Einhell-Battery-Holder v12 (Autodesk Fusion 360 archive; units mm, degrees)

design "Einhell-Battery-Holder" references "Base"
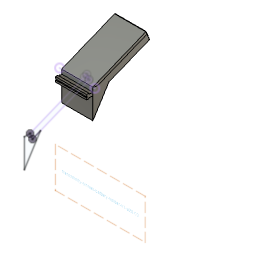
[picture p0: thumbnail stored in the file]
parameter "angle" = 20
component_insert "Component Insert"
sketch "Sketch1" plane through (0, 55.6118, 0) normal (0, 1, 0) x axis (-1, 0, 0)
  line L1 (0, 52.6059) -> (-62, 52.6059)
  line L2 (0, 60) -> (0, 52.6059)
  line L3 (-62, 60) -> (0, 60)
  line L4 (-62, 52.6059) -> (-62, 60)
  line L5 (-62, 60) -> (0, 60)
base_mesh_feature "Base Mesh Feature"
modify "Modify1"
modify "Modify2"
convert_mesh "Convert Mesh" bodies "Einhell_French_Cleat"
delete_face "DeleteFace1"
delete_face "DeleteFace2"
delete_face "DeleteFace3"
delete_face "DeleteFace4"
delete_face "DeleteFace5"
delete_face "DeleteFace6"
delete_face "DeleteFace7"
delete_face "DeleteFace8"
delete_face "DeleteFace9"
delete_face "DeleteFace10"
delete_face "DeleteFace11"
delete_face "DeleteFace12"
delete_face "DeleteFace13"
delete_face "DeleteFace14"
delete_face "DeleteFace15"
delete_face "DeleteFace16"
sketch "Sketch2" plane through (43.2707, 0, 0) normal (1, 0, 0) x axis (0, 1, 0)
  line L1 (75.5556, 48.0301) -> (76.5556, 47.0301)
  line L2 (48.0556, 48.0301) -> (75.5556, 48.0301)
  line L3 (48.0556, 26.0301) -> (48.0556, 48.0301)
  line L4 (65.0556, 43.0301) -> (48.0556, 26.0301)
  line L5 (65.0556, 0.0301) -> (65.0556, 43.0301)
  line L6 (76.5556, 0.0301) -> (65.0556, 0.0301)
  line L7 (76.5556, 47.0301) -> (76.5556, 0.0301)
  line L8 (65.0556, 48.0301) -> (65.0556, 43.0301)
  point P6 (65.0556, 43.0301)
  point P9 (65.0556, 43.0301)
  point P10 (65.0556, 48.0301)
  coincident P6 P9
  coincident L2 P10
  perpendicular L2 L8
extrude "Extrude1" cut sketch "Sketch2" profile of L2 L3 L4 L8 to an object
work_plane "WorkPlane1" AlongDistance -55
split "Split1"
move "Move1"
sketch "Filename" plane through (0, 0, 0) normal (0, 1, 0) x axis (1, 0, 0)
  dimension "d12" = 5
move "Move2"
extrude "Extrude6" add of existing geometry blind 60
extrude "Extrude7" new body of existing geometry blind 20
extrude "Extrude8" add of existing geometry to an object
extrude "Extrude9" cut of existing geometry to an object
sketch "Sketch5" plane through (3.5, 0, 0) normal (-1, 0, 0) x axis (0, -1, 0)
  line L1 (-4.2888, -21.139) -> (-103.4974, 18.9439)
  line L2 (0.0192, -10.4764) -> (-4.2888, -21.139)
  line L3 (-95.4807, 28.1081) -> (0.0192, -10.4764)
  line L4 (-100.1167, 29.9811) -> (-95.4807, 28.1081)
  line L5 (-104.05, 20.2457) -> (-100.1167, 29.9811)
  line L6 (-103.4974, 18.9439) -> (-104.05, 20.2457)
  line L7 (10.0192, -10.4764) -> (0.0192, -10.4764)
  line L8 (10.0192, -60.4764) -> (10.0192, -10.4764)
  line L9 (-18.1965, -15.5199) -> (-4.2888, -21.139)
  line L10 (10.0192, -60.4764) -> (-18.1965, -15.5199)
  point P4 (0.0192, -10.4764)
  point P8 (0.0192, -10.4764)
  point P3 (-4.2888, -21.139)
  point P11 (-4.2888, -21.139)
  point P9 (10.0192, -10.4764)
  point P10 (10.0192, -60.4764)
  point P12 (-18.1965, -15.5199)
  coincident P4 P8
  horizontal L7
  perpendicular L7 L8
  coincident P3 P11
  perpendicular L2 L9
  dimension "d24" distance P8 P9 = 10
  dimension "d25" distance P9 P10 = 50
  dimension "d27" distance P11 P12 = 15
extrude "Extrude10" add sketch "Sketch5" profile of L1 L2 L7 L8 L9 L10 to an object
extrude "Extrude11" add of existing geometry blind 5
extrude "Extrude12" add of existing geometry to an object
move "Move3"
extrude "Extrude13" add of existing geometry to an object
extrude "Extrude14" add of existing geometry to an object
extrude "Extrude15" add of existing geometry to an object
extrude "Extrude16" add of existing geometry to an object
extrude "Extrude17" add of existing geometry blind -15
sketch "Sketch6" plane through (0, -9.6643, 23.9199) normal (0, 0.3746, -0.9272) x axis (-1, 0, 0)
  line L1 (-55.5, 142.804) -> (-55.5, 190.804)
  line L2 (-55.5, 97.804) -> (-55.5, 142.804)
  line L3 (-6.5, 97.804) -> (-55.5, 97.804)
  line L4 (-6.5, 190.804) -> (-6.5, 97.804)
  line L5 (-55.5, 190.804) -> (-6.5, 190.804)
  curve K1
  curve K2
  curve K3
  curve K4
  point P5 (-6.5, 97.804)
  point P2 (-55.5, 190.804)
  coincident P5
  coincident P2
  dimension "d44" Text1-Height = 3
extrude "Extrude18" cut sketch "Sketch6" along a picked direction blind -2
extrude "Extrude19" add of existing geometry blind -10
extrude "Extrude20" cut of existing geometry blind -15
extrude "Extrude21" cut of existing geometry blind -12
fillet "Fillet2" radius 1
named bodies: "Einhell_French_Cleat", "Einhell_French_Cleat (1)"

design "Base"
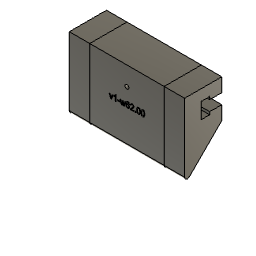
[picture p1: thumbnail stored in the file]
parameter "wall_anchor_height" = 60
parameter "wall_anchor_width" = 20
parameter "wall_anchor_angle" = 45
parameter "width_per_slot" = 40
parameter "slot_inner_width" = 8.5
parameter "slot_inner_height" = 4.5
parameter "slot_outer_width" = 5.6
parameter "slot_outer_height" = 6.5
parameter "slot_dept" = 15
parameter "print_tolerance" = 0.12
parameter "base_plate_thickness" = 16
parameter "base_plate_slot_height" = 50
parameter "wall_anchor_angle_rounded_border" = 1.5
parameter "base_plate_screw_hole_diameter" = 4
parameter "base_plate_screw_head_diameter" = 8
parameter "base_plate_screw_head_height" = 4
parameter "base_plate_screw_hole_side_distance" = 7
parameter "slot_screw_head_width" = 4.42 (= "4.3 mm + print_tolerance")
parameter "slot_screw_thread_width" = 2.12 (= "2 mm + print_tolerance")
parameter "slot_screw_head_height" = 2.12 (= "2 mm + print_tolerance")
parameter "width" = 62
parameter "filament_hole_width" = 1.7
sketch "Side" plane through (0, 0, 0) normal (1, 0, 0) x axis (0, 1, 0)
  line L1 (39.6118, 0) -> (19.6118, 0)
  line L2 (39.6118, 60) -> (39.6118, 0)
  line L3 (19.6118, 60) -> (39.6118, 60)
  line L4 (19.6118, 0) -> (19.6118, 60)
  line L5 (39.6118, 39.6118) -> (0, 0)
  line L6 (56.0196, 0) -> (0, 0)
  point P1 (0, 0)
  point P6 (0, 0)
  point P7 (39.6118, 39.6118)
  point P2 (19.6118, 0)
  point P3 (39.6118, 0)
  point P5 (19.6118, 60)
  horizontal L1
  vertical L2
  horizontal L3
  vertical L4
  horizontal L6
  coincident P1 P6
  coincident L2 P7
  dimension "d4" distance P2 P3 = 20 (= "wall_anchor_width")
  dimension "d5" distance P2 P5 = 60 (= "wall_anchor_height")
  dimension "d6" angle L5 L6 = 45 (= "wall_anchor_angle")
extrude "Extrude1" new body sketch "Side" profile of L1 L2 L3 L4 L5 along normal blind 40 (= "width_per_slot")
sketch "Slot LeftToRight" plane through (0, 0, 0) normal (-1, 0, 0) x axis (0, -1, 0)
  line L1 (-19.6118, 60) -> (-19.6118, 19.6118)
  line L2 (-39.6118, 60) -> (-19.6118, 60)
  line L3 (-39.6118, 39.6118) -> (-39.6118, 60)
  line L4 (-19.6118, 19.6118) -> (-39.6118, 39.6118)
  line L5 (-39.6118, 52.6059) -> (-39.6118, 49.8059)
  line L6 (-39.6118, 47.0059) -> (-39.6118, 49.8059)
  line L7 (-33.1118, 52.6059) -> (-39.6118, 52.6059)
  line L8 (-28.6118, 49.8059) -> (-39.6118, 49.8059)
  line L9 (-28.6118, 54.0559) -> (-28.6118, 49.8059)
  line L10 (-33.1118, 54.0559) -> (-28.6118, 54.0559)
  line L11 (-33.1118, 52.6059) -> (-33.1118, 54.0559)
  line L12 (-28.6118, 45.5559) -> (-28.6118, 49.8059)
  line L13 (-33.1118, 45.5559) -> (-28.6118, 45.5559)
  line L14 (-33.1118, 47.0059) -> (-33.1118, 45.5559)
  line L15 (-33.1118, 47.0059) -> (-39.6118, 47.0059)
  point P6 (-39.6118, 49.8059)
  point P7 (-39.6118, 52.6059)
  point P17 (-39.6118, 47.0059)
  point P9 (-33.1118, 52.6059)
  point P16 (-33.1118, 47.0059)
  point P10 (-28.6118, 49.8059)
  point P13 (-28.6118, 49.8059)
  point P11 (-28.6118, 54.0559)
  point P14 (-28.6118, 45.5559)
  point P12 (-33.1118, 54.0559)
  point P15 (-33.1118, 45.5559)
  midpoint L3 P6
  parallel L3 L5
  parallel L3 L6
  perpendicular L3 L7
  perpendicular L6 L8
  perpendicular L8 L9
  perpendicular L9 L10
  symmetric P7 L8 P17
  symmetric P9 L8 P16
  symmetric P10 L8 P13
  symmetric L8 P11 P14
  symmetric L8 P12 P15
  dimension "d80" distance P6 P7 = 2.8 (= "slot_outer_width / 2")
  dimension "d82" distance P7 P9 = 6.5 (= "slot_outer_height")
  dimension "d84" distance P6 P10 = 11 (= "slot_outer_height + slot_inner_height")
  dimension "d85" distance P10 P11 = 4.25 (= "slot_inner_width / 2")
  dimension "d86" distance P11 P12 = 4.5 (= "slot_inner_height")
extrude "Extrude3" cut sketch "Slot LeftToRight" profile of L3 L5 L6 L7 L9 L10 L11 L12 L13 L14 L15 against normal blind 40 (magnitude of "width_per_slot * -1")
sketch "Plate" plane through (0, 39.6118, 0) normal (0, 1, 0) x axis (-1, 0, 0)
  line L1 (0, 39.6118) -> (-40, 39.6118)
  line L2 (-40, 60) -> (0, 60)
  line L3 (0, 10) -> (0, 60)
  line L4 (-40, 10) -> (-40, 60)
  line L5 (-40, 10) -> (0, 10)
  line L6 (-40, 47.0059) -> (0, 47.0059)
  line L7 (-40, 52.6059) -> (-40, 60)
  line L8 (0, 60) -> (0, 52.6059)
  line L9 (0, 52.6059) -> (-40, 52.6059)
  line L10 (-40, 60) -> (0, 60)
  line L11 (-40, 39.6118) -> (-40, 47.0059)
  line L12 (0, 47.0059) -> (0, 39.6118)
  point P2 (0, 60)
  point P3 (-40, 60)
  point P4 (0, 10)
  point P5 (-40, 10)
  perpendicular L1 L3
  perpendicular L1 L4
  dimension "d36" distance P2 P3 = 40 (= "width_per_slot")
  dimension "d37" distance P2 P4 = 50 (= "base_plate_slot_height")
  dimension "d39" distance P3 P5 = 50 (= "base_plate_slot_height")
extrude "Extrude6" new body sketch "Plate" profile of L1 L2 L3 L4 L5 L6 L7 L8 L9 L10 along normal blind 16 (= "base_plate_thickness") bodies "Base plate with slot"
sketch "Slot" plane through (0, 0, 0) normal (-1, 0, 0) x axis (0, -1, 0)
  line L1 (-19.6118, 60) -> (-19.6118, 19.6118)
  line L2 (-39.6118, 60) -> (-19.6118, 60)
  line L3 (-39.6118, 52.6059) -> (-39.6118, 60)
  line L4 (-33.1118, 52.6059) -> (-39.6118, 52.6059)
  line L5 (-33.1118, 54.0559) -> (-33.1118, 52.6059)
  line L6 (-28.6118, 54.0559) -> (-33.1118, 54.0559)
  line L7 (-28.6118, 45.5559) -> (-28.6118, 54.0559)
  line L8 (-33.1118, 45.5559) -> (-28.6118, 45.5559)
  line L9 (-33.1118, 47.0059) -> (-33.1118, 45.5559)
  line L10 (-39.6118, 47.0059) -> (-33.1118, 47.0059)
  line L11 (-39.6118, 39.6118) -> (-39.6118, 47.0059)
  line L12 (-19.6118, 19.6118) -> (-39.6118, 39.6118)
  line L13 (-33.1118, 52.6059) -> (-39.6118, 52.6059)
  line L14 (-33.1118, 54.0559) -> (-33.1118, 52.6059)
  line L15 (-28.6118, 54.0559) -> (-33.1118, 54.0559)
  line L16 (-28.6118, 45.5559) -> (-28.6118, 54.0559)
  line L17 (-33.1118, 45.5559) -> (-28.6118, 45.5559)
  line L18 (-33.1118, 47.0059) -> (-33.1118, 45.5559)
  line L19 (-39.6118, 47.0059) -> (-33.1118, 47.0059)
  line L20 (-39.6118, 10) -> (-39.6118, 60)
  line L21 (-32.9918, 52.4859) -> (-39.6118, 52.4859)
  line L22 (-32.9918, 53.9359) -> (-32.9918, 52.4859)
  line L23 (-28.7318, 53.9359) -> (-32.9918, 53.9359)
  line L24 (-28.7318, 45.6759) -> (-28.7318, 53.9359)
  line L25 (-32.9918, 45.6759) -> (-28.7318, 45.6759)
  line L26 (-32.9918, 47.1259) -> (-32.9918, 45.6759)
  line L27 (-39.6118, 47.1259) -> (-32.9918, 47.1259)
  line L28 (-33.1118, 52.6059) -> (-39.6118, 52.6059)
  line L29 (-33.1118, 52.6059) -> (-33.1118, 54.0559)
  line L30 (-28.6118, 54.0559) -> (-33.1118, 54.0559)
  line L31 (-28.6118, 45.5559) -> (-28.6118, 54.0559)
  line L32 (-33.1118, 45.5559) -> (-28.6118, 45.5559)
  line L33 (-33.1118, 47.0059) -> (-33.1118, 45.5559)
  line L34 (-39.6118, 47.0059) -> (-33.1118, 47.0059)
  line L35 (-39.6118, 47.0059) -> (-39.6118, 52.6059)
  line L36 (-49.1118, 52.6059) -> (-55.6118, 52.6059)
  line L37 (-49.1118, 52.6059) -> (-49.1118, 54.0559)
  line L38 (-44.6118, 54.0559) -> (-49.1118, 54.0559)
  line L39 (-44.6118, 45.5559) -> (-44.6118, 54.0559)
  line L40 (-49.1118, 45.5559) -> (-44.6118, 45.5559)
  line L41 (-49.1118, 47.0059) -> (-49.1118, 45.5559)
  line L42 (-55.6118, 47.0059) -> (-49.1118, 47.0059)
  line L43 (-55.6118, 47.0059) -> (-55.6118, 52.6059)
  point P15 (-39.6118, 52.6059)
  point P33 (-39.6118, 52.6059)
  point P16 (-33.1118, 52.6059)
  point P34 (-33.1118, 52.6059)
  point P17 (-33.1118, 54.0559)
  point P35 (-33.1118, 54.0559)
  point P36 (-33.1118, 52.6059)
  point P18 (-28.6118, 54.0559)
  point P37 (-28.6118, 54.0559)
  point P19 (-28.6118, 45.5559)
  point P38 (-28.6118, 45.5559)
  point P10 (-28.6118, 45.5559)
  point P39 (-28.6118, 45.5559)
  point P11 (-33.1118, 45.5559)
  point P40 (-33.1118, 45.5559)
  point P41 (-33.1118, 45.5559)
  point P12 (-33.1118, 47.0059)
  point P42 (-33.1118, 47.0059)
  point P21 (-33.1118, 47.0059)
  point P43 (-33.1118, 47.0059)
  point P22 (-39.6118, 47.0059)
  point P44 (-39.6118, 47.0059)
  point P45 (-39.6118, 52.6059)
  point P46 (-39.6118, 47.0059)
  coincident P15 P33
  coincident P16 P34
  coincident P17 P35
  coincident P16 P36
  coincident P18 P37
  coincident P19 P38
  coincident P10 P39
  coincident P11 P40
  coincident P11 P41
  coincident P12 P42
  coincident P21 P43
  coincident P22 P44
  coincident P15 P45
  coincident P22 P46
  dimension "d91" = 0.12 (= "print_tolerance")
  dimension "d96" R-Pattern1-uDistance = -16 (= "base_plate_thickness * -1")
  dimension "d97" R-Pattern1-vDistance = 0
extrude "Extrude7" add sketch "Slot" profile of L20 L24 L23 L27 L22 L25 L26 L21 against normal blind 40 (magnitude of "width_per_slot * -1")
extrude "Extrude8" cut sketch "Slot" profile of L36 L37 L38 L39 L40 L41 L42 L43 no distance stored
sketch "Sketch3" plane through (0, 0, 0) normal (-1, 0, 0) x axis (0, -1, 0)
  line L1 (-32.9918, 47.1259) -> (-39.6118, 47.1259)
  line L2 (-32.9918, 45.6759) -> (-32.9918, 47.1259)
  line L3 (-28.7318, 45.6759) -> (-32.9918, 45.6759)
  line L4 (-28.7318, 53.9359) -> (-28.7318, 45.6759)
  line L5 (-32.9918, 53.9359) -> (-28.7318, 53.9359)
  line L6 (-32.9918, 52.4859) -> (-32.9918, 53.9359)
  line L7 (-39.6118, 52.4859) -> (-32.9918, 52.4859)
  line L8 (-44.6118, 45.5559) -> (-44.6118, 54.0559)
  line L9 (-32.9918, 52.4859) -> (-39.6118, 52.4859)
  line L10 (-32.9918, 53.9359) -> (-32.9918, 52.4859)
  line L11 (-28.7318, 53.9359) -> (-32.9918, 53.9359)
  line L12 (-28.7318, 45.6759) -> (-28.7318, 53.9359)
  line L13 (-32.9918, 45.6759) -> (-28.7318, 45.6759)
  line L14 (-32.9918, 47.1259) -> (-32.9918, 45.6759)
  line L15 (-39.6118, 47.1259) -> (-32.9918, 47.1259)
  line L16 (-39.6118, 47.1259) -> (-39.6118, 52.4859)
  line L17 (-55.6118, 52.4859) -> (-48.9918, 52.4859)
  line L18 (-48.9918, 52.4859) -> (-48.9918, 53.9359)
  line L19 (-48.9918, 53.9359) -> (-44.7318, 53.9359)
  line L20 (-44.7318, 45.6759) -> (-44.7318, 53.9359)
  line L21 (-48.9918, 45.6759) -> (-44.7318, 45.6759)
  line L22 (-48.9918, 47.1259) -> (-48.9918, 45.6759)
  line L23 (-55.6118, 47.1259) -> (-48.9918, 47.1259)
  line L24 (-55.6118, 47.1259) -> (-55.6118, 52.4859)
  line L25 (-55.6118, 47.0059) -> (-49.1118, 47.0059)
  line L26 (-55.6118, 10) -> (-55.6118, 47.0059)
  line L27 (-39.6118, 10) -> (-55.6118, 10)
  line L28 (-39.6118, 47.1259) -> (-39.6118, 10)
  line L29 (-39.6118, 60) -> (-39.6118, 52.4859)
  line L30 (-55.6118, 60) -> (-39.6118, 60)
  line L31 (-55.6118, 52.6059) -> (-55.6118, 60)
  line L32 (-49.1118, 52.6059) -> (-55.6118, 52.6059)
  line L33 (-49.1118, 54.0559) -> (-49.1118, 52.6059)
  line L34 (-44.6118, 54.0559) -> (-49.1118, 54.0559)
  line L35 (-49.1118, 45.5559) -> (-44.6118, 45.5559)
  line L36 (-49.1118, 47.0059) -> (-49.1118, 45.5559)
  point P9 (-39.6118, 52.4859)
  point P20 (-39.6118, 52.4859)
  point P19 (-39.6118, 47.1259)
  point P21 (-39.6118, 47.1259)
  coincident P9 P20
  coincident P19 P21
  dimension "d105" R-Pattern1-vDistance = 0
extrude "Extrude3" new body sketch "Sketch3" profile of L17 L18 L19 L20 L21 L22 L23 L24 against normal blind 40 (magnitude of "width_per_slot * -1")
sketch "Screw hole" plane through (0, 28.6118, 0) normal (0, 1, 0) x axis (-1, 0, 0)
  line L1 (0, 54.0559) -> (0, 45.5559)
  line L2 (-40, 54.0559) -> (0, 54.0559)
  line L3 (-40, 45.5559) -> (-40, 54.0559)
  line L4 (0, 45.5559) -> (-40, 45.5559)
  line L5 (0, 45.5559) -> (-40, 54.0559)
  line L6 (-40, 45.5559) -> (0, 54.0559)
  circle C1 centre (-20, 49.8059) radius 2.21
  circle C2 centre (-20, 49.8059) radius 1.06
  point P4 (-40, 54.0559)
  point P6 (-40, 54.0559)
  point P2 (0, 45.5559)
  point P7 (0, 45.5559)
  point P3 (0, 54.0559)
  point P8 (0, 54.0559)
  point P5 (-40, 45.5559)
  point P9 (-40, 45.5559)
  point P10 (-20, 49.8059)
  coincident P4 P6
  coincident P2 P7
  coincident P3 P8
  coincident P5 P9
  midpoint L5 P10
  concentric C1 C2
  dimension "d119" diameter C1 = 4.42 (= "slot_screw_head_width")
  dimension "d120" diameter C2 = 2.12 (= "slot_screw_thread_width")
extrude "Extrude4" cut sketch "Screw hole" profile of C2 against normal blind 2000
extrude "Extrude5" cut sketch "Screw hole" profile of C1 C2 no distance stored
fillet "Fillet1" radius 1.5 (= "wall_anchor_angle_rounded_border")
work_plane "WorkPlane1" sketch "Slot LeftToRight" AlongDistance -20 (= "-width_per_slot / 2")
sketch "Screw head" plane through (20, 0, 0) normal (-1, 0, 0) x axis (0, -1, 0)
  line L1 (-28.6118, 52.0159) -> (-28.6118, 47.5959)
  line L2 (-26.4918, 52.0159) -> (-26.4918, 47.5959)
  line L3 (-26.4918, 48.7459) -> (-26.4918, 50.8659)
  line L4 (-26.4918, 50.8659) -> (-28.6118, 52.0159)
  line L5 (-26.4918, 52.0159) -> (-28.6118, 52.0159)
  point P3 (-28.6118, 52.0159)
  point P8 (-28.6118, 52.0159)
  point P6 (-26.4918, 50.8659)
  point P9 (-26.4918, 50.8659)
  point P10 (-28.6118, 52.0159)
  point P5 (-26.4918, 52.0159)
  point P11 (-26.4918, 52.0159)
  coincident P3 P8
  coincident P6 P9
  coincident P3 P10
  coincident P5 P11
revolve "Revolve1" sketch "Screw head" AlongAngle 360
sketch "Plate" plane through (0, 39.6118, 0) normal (0, 1, 0) x axis (-1, 0, 0)
  line L1 (0, 39.6118) -> (-40, 39.6118)
  line L2 (-40, 60) -> (0, 60)
  line L3 (0, 10) -> (0, 60)
  line L4 (-40, 10) -> (-40, 60)
  line L5 (-40, 10) -> (0, 10)
  line L6 (-40, 47.0059) -> (0, 47.0059)
  line L7 (-40, 39.6118) -> (-40, 47.0059)
  line L8 (0, 47.0059) -> (0, 39.6118)
  line L9 (0, 52.6059) -> (-40, 52.6059)
  line L10 (-40, 60) -> (0, 60)
  line L11 (0, 60) -> (0, 52.6059)
  line L12 (-40, 52.6059) -> (-40, 60)
  point P2 (0, 60)
  point P3 (-40, 60)
  point P4 (0, 10)
  point P5 (-40, 10)
  perpendicular L1 L3
  perpendicular L1 L4
  dimension "d36_1" distance P2 P3 = 40 (= "width_per_slot")
  dimension "d37_1" distance P2 P4 = 50 (= "base_plate_slot_height")
  dimension "d39_1" distance P3 P5 = 50 (= "base_plate_slot_height")
extrude "Extrude6" new body sketch "Plate" profile of L1 L2 L3 L4 L5 L6 L7 L8 L9 L10 along normal blind 16 (= "base_plate_thickness") named "d89_1" bodies "Base plate with slot"
sketch "Slot" plane through (0, 0, 0) normal (-1, 0, 0) x axis (0, -1, 0)
  line L1 (-19.6118, 60) -> (-19.6118, 23.2332)
  line L2 (-39.6118, 60) -> (-19.6118, 60)
  line L3 (-39.6118, 52.6059) -> (-39.6118, 60)
  line L4 (-33.1118, 52.6059) -> (-39.6118, 52.6059)
  line L5 (-33.1118, 54.0559) -> (-33.1118, 52.6059)
  line L6 (-28.6118, 54.0559) -> (-33.1118, 54.0559)
  line L7 (-28.6118, 45.5559) -> (-28.6118, 54.0559)
  line L8 (-33.1118, 45.5559) -> (-28.6118, 45.5559)
  line L9 (-33.1118, 47.0059) -> (-33.1118, 45.5559)
  line L10 (-39.6118, 47.0059) -> (-33.1118, 47.0059)
  line L11 (-39.6118, 39.6118) -> (-39.6118, 47.0059)
  line L12 (-22.1725, 22.1725) -> (-39.6118, 39.6118)
  line L13 (-33.1118, 52.6059) -> (-39.6118, 52.6059)
  line L14 (-33.1118, 54.0559) -> (-33.1118, 52.6059)
  line L15 (-28.6118, 54.0559) -> (-33.1118, 54.0559)
  line L16 (-28.6118, 45.5559) -> (-28.6118, 54.0559)
  line L17 (-33.1118, 45.5559) -> (-28.6118, 45.5559)
  line L18 (-33.1118, 47.0059) -> (-33.1118, 45.5559)
  line L19 (-39.6118, 47.0059) -> (-33.1118, 47.0059)
  line L20 (-39.6118, 10) -> (-39.6118, 60)
  line L21 (-32.9918, 52.4859) -> (-39.6118, 52.4859)
  line L22 (-32.9918, 53.9359) -> (-32.9918, 52.4859)
  line L23 (-28.7318, 53.9359) -> (-32.9918, 53.9359)
  line L24 (-28.7318, 45.6759) -> (-28.7318, 53.9359)
  line L25 (-32.9918, 45.6759) -> (-28.7318, 45.6759)
  line L26 (-32.9918, 47.1259) -> (-32.9918, 45.6759)
  line L27 (-39.6118, 47.1259) -> (-32.9918, 47.1259)
  line L28 (-33.1118, 52.6059) -> (-39.6118, 52.6059)
  line L29 (-33.1118, 52.6059) -> (-33.1118, 54.0559)
  line L30 (-28.6118, 54.0559) -> (-33.1118, 54.0559)
  line L31 (-28.6118, 45.5559) -> (-28.6118, 54.0559)
  line L32 (-33.1118, 45.5559) -> (-28.6118, 45.5559)
  line L33 (-33.1118, 47.0059) -> (-33.1118, 45.5559)
  line L34 (-39.6118, 47.0059) -> (-33.1118, 47.0059)
  line L35 (-39.6118, 47.0059) -> (-39.6118, 52.6059)
  line L36 (-49.1118, 52.6059) -> (-55.6118, 52.6059)
  line L37 (-49.1118, 52.6059) -> (-49.1118, 54.0559)
  line L38 (-44.6118, 54.0559) -> (-49.1118, 54.0559)
  line L39 (-44.6118, 45.5559) -> (-44.6118, 54.0559)
  line L40 (-49.1118, 45.5559) -> (-44.6118, 45.5559)
  line L41 (-49.1118, 47.0059) -> (-49.1118, 45.5559)
  line L42 (-55.6118, 47.0059) -> (-49.1118, 47.0059)
  line L43 (-55.6118, 47.0059) -> (-55.6118, 52.6059)
  arc A1 centre (-21.1118, 23.2332) radius 1.5 clockwise from (-19.6118, 23.2332) to (-22.1725, 22.1725)
  point P15 (-39.6118, 52.6059)
  point P33 (-39.6118, 52.6059)
  point P16 (-33.1118, 52.6059)
  point P34 (-33.1118, 52.6059)
  point P17 (-33.1118, 54.0559)
  point P35 (-33.1118, 54.0559)
  point P36 (-33.1118, 52.6059)
  point P18 (-28.6118, 54.0559)
  point P37 (-28.6118, 54.0559)
  point P19 (-28.6118, 45.5559)
  point P38 (-28.6118, 45.5559)
  point P10 (-28.6118, 45.5559)
  point P39 (-28.6118, 45.5559)
  point P11 (-33.1118, 45.5559)
  point P40 (-33.1118, 45.5559)
  point P41 (-33.1118, 45.5559)
  point P12 (-33.1118, 47.0059)
  point P42 (-33.1118, 47.0059)
  point P21 (-33.1118, 47.0059)
  point P43 (-33.1118, 47.0059)
  point P22 (-39.6118, 47.0059)
  point P44 (-39.6118, 47.0059)
  point P45 (-39.6118, 52.6059)
  point P46 (-39.6118, 47.0059)
  coincident P15 P33
  coincident P16 P34
  coincident P17 P35
  coincident P16 P36
  coincident P18 P37
  coincident P19 P38
  coincident P10 P39
  coincident P11 P40
  coincident P11 P41
  coincident P12 P42
  coincident P21 P43
  coincident P22 P44
  coincident P15 P45
  coincident P22 P46
  dimension "d91_1" = 0.12 (= "print_tolerance")
  dimension "d96_1" R-Pattern1-uDistance = -16 (= "base_plate_thickness * -1")
  dimension "d97_1" R-Pattern1-vDistance = 0
extrude "Extrude8" cut sketch "Slot" profile of L36 L37 L38 L39 L40 L41 L42 L43 no distance stored
sketch "Screw" plane through (0, 55.6118, 0) normal (0, 1, 0) x axis (-1, 0, 0)
  line L1 (-40, 47.0059) -> (0, 47.0059)
  line L2 (-40, 10) -> (-40, 47.0059)
  line L3 (0, 10) -> (-40, 10)
  line L4 (0, 47.0059) -> (0, 10)
  line L5 (-33, 17) -> (-33, 40.0059)
  line L6 (-7, 17) -> (-33, 17)
  line L7 (-7, 40.0059) -> (-7, 17)
  line L8 (-33, 40.0059) -> (-7, 40.0059)
  circle C1 centre (-33, 17) radius 4
  circle C2 centre (-33, 17) radius 2
  point P7 (-33, 17)
  point P10 (-33, 17)
  coincident P7 P10
  concentric C1 C2
  dimension "d127" = -7 (= "base_plate_screw_hole_side_distance * -1")
  dimension "d128" diameter C1 = 8
  dimension "d129" diameter C2 = 4
rectangular_pattern "R-Pattern2" countU 1 (= "floor(( width / mm ) / ( width_per_slot / cm * 10 ))") uSpaceDistance 40 (= "width_per_slot") vSpaceDistance 0
work_plane "WorkPlane2"
extrude "Extrude12" new body of existing geometry no distance stored
mirror "Mirror3" mirrorStitchTolerance 0.1
sketch "filename" plane through (0, 19.6118, 0) normal (0, -1, 0) x axis (1, 0, 0)
  dimension "d216" = 3
sketch "Sketch14" plane through (0, 19.6118, 0) normal (0, -1, 0) x axis (1, 0, 0)
  line L1 (51, 60) -> (51, 23.2332)
  line L2 (40, 23.2332) -> (40, 60)
  line L3 (51, 23.2332) -> (40, 23.2332)
  line L4 (51, 60) -> (51, 23.2332)
  line L5 (40, 60) -> (51, 60)
  line L6 (0, 60) -> (0, 23.2332)
  line L7 (-11, 60) -> (0, 60)
  line L8 (-11, 23.2332) -> (-11, 60)
  line L9 (0, 23.2332) -> (-11, 23.2332)
  curve K1
  curve K2
  curve K3
  curve K4
  point P4 (51, 23.2332)
  point P2 (-11, 60)
  coincident P4
  coincident P2
  dimension "d229" Text1-Height = 3
extrude "Extrude19" cut sketch "Sketch14" against normal blind 2
extrude "Extrude14" cut of existing geometry blind 11 (= "( width_per_slot - width ) / -2")
extrude "Extrude15" cut of existing geometry blind 11 (= "( width_per_slot - width ) / -2")
extrude "Extrude9" cut of existing geometry blind -39 (= "-width_per_slot + 1 mm")
extrude "Extrude10" add of existing geometry blind 61 (= "width - 1 mm")
sketch "Sketch7" plane through (0, 39.6118, 0) normal (0, -1, 0) x axis (1, 0, 0)
  dimension "d236" = 3
extrude "Extrude11" cut sketch "Sketch7" against normal blind 2
sketch "File name" plane through (0, 39.6118, 0) normal (0, -1, 0) x axis (1, 0, 0)
  line L1 (25.0624, 30.0752) -> (24.825, 30.0752)
  line L2 (25.0624, 27.063) -> (25.0624, 30.0752)
  line L3 (24.6941, 27.063) -> (25.0624, 27.063)
  line L4 (24.6941, 29.4102) -> (24.6941, 27.063)
  curve K1 (24.3441, 29.1564) -> (24.6941, 29.4102)
  curve K2 (23.9574, 28.9661) -> (24.3441, 29.1564)
  line L5 (23.9574, 29.3222) -> (23.9574, 28.9661)
  curve K3 (24.4976, 29.6741) -> (23.9574, 29.3222)
  curve K4 (24.825, 30.0752) -> (24.4976, 29.6741)
  line L6 (28.2896, 27.063) -> (28.7295, 28.7349)
  line L7 (27.9048, 27.063) -> (28.2896, 27.063)
  line L8 (27.2398, 29.2362) -> (27.9048, 27.063)
  line L9 (27.6204, 29.2362) -> (27.2398, 29.2362)
  line L10 (27.9662, 27.9818) -> (27.6204, 29.2362)
  line L11 (28.0952, 27.5152) -> (27.9662, 27.9818)
  curve K5 (28.2077, 27.9634) -> (28.0952, 27.5152)
  line L12 (28.5535, 29.2362) -> (28.2077, 27.9634)
  line L13 (28.9321, 29.2362) -> (28.5535, 29.2362)
  line L14 (29.2575, 27.9756) -> (28.9321, 29.2362)
  line L15 (29.366, 27.5602) -> (29.2575, 27.9756)
  line L16 (29.4908, 27.9797) -> (29.366, 27.5602)
  line L17 (29.8632, 29.2362) -> (29.4908, 27.9797)
  line L18 (30.2213, 29.2362) -> (29.8632, 29.2362)
  line L19 (29.5419, 27.063) -> (30.2213, 29.2362)
  line L20 (29.1593, 27.063) -> (29.5419, 27.063)
  line L21 (28.8134, 28.3645) -> (29.1593, 27.063)
  line L22 (28.7295, 28.7349) -> (28.8134, 28.3645)
  line L23 (27.0965, 27.9634) -> (27.0965, 28.3338)
  line L24 (25.9649, 27.9634) -> (27.0965, 27.9634)
  line L25 (25.9649, 28.3338) -> (25.9649, 27.9634)
  line L26 (27.0965, 28.3338) -> (25.9649, 28.3338)
  line L27 (22.6293, 27.063) -> (23.4519, 29.2362)
  line L28 (22.2855, 27.063) -> (22.6293, 27.063)
  line L29 (21.4587, 29.2362) -> (22.2855, 27.063)
  line L30 (21.8475, 29.2362) -> (21.4587, 29.2362)
  line L31 (22.3141, 27.9347) -> (21.8475, 29.2362)
  curve K6 (22.4533, 27.4968) -> (22.3141, 27.9347)
  curve K7 (22.5904, 27.9102) -> (22.4533, 27.4968)
  line L32 (23.0733, 29.2362) -> (22.5904, 27.9102)
  line L33 (23.4519, 29.2362) -> (23.0733, 29.2362)
  line L34 (0, 47.1259) -> (62, 47.1259)
  line L35 (0, 10) -> (0, 47.1259)
  line L36 (62, 10) -> (0, 10)
  line L37 (62, 47.1259) -> (62, 10)
  curve K8
  curve K9
  curve K10
  curve K11
  curve K12 (30.7329, 29.7314) -> (30.4117, 28.4668)
  curve K13 (31.4656, 29.7724) -> (31.8339, 29.6148)
  curve K14 (31.1565, 29.6741) -> (31.4656, 29.7724)
  curve K15 (30.778, 28.61) -> (30.8823, 29.3037)
  curve K16 (31.1033, 28.9108) -> (30.778, 28.61)
  curve K17 (31.8339, 29.6148) -> (31.9731, 29.2997)
  curve K18 (30.8823, 29.3037) -> (31.1565, 29.6741)
  curve K19 (31.5065, 29.0091) -> (31.1033, 28.9108)
  curve K20 (32.0672, 29.8767) -> (31.4881, 30.0752)
  curve K21 (32.3394, 29.3283) -> (32.0672, 29.8767)
  line L38 (31.9731, 29.2997) -> (32.3394, 29.3283)
  curve K22 (39.5631, 30.0752) -> (39.0188, 29.8992)
  curve K23 (39.9867, 29.977) -> (39.5631, 30.0752)
  curve K24 (38.6934, 29.3979) -> (38.5849, 28.5425)
  curve K25 (39.0188, 29.8992) -> (38.6934, 29.3979)
  curve K26 (33.4792, 28.1721) -> (32.9962, 27.7178)
  curve K27 (34.1402, 28.8065) -> (33.4792, 28.1721)
  curve K28 (32.7548, 27.3188) -> (32.7118, 27.063)
  curve K29 (32.9962, 27.7178) -> (32.7548, 27.3188)
  curve K30 (37.2323, 30.0752) -> (36.6879, 29.8992)
  curve K31 (37.6559, 29.977) -> (37.2323, 30.0752)
  curve K32 (36.3626, 29.3979) -> (36.2541, 28.5425)
  curve K33 (36.6879, 29.8992) -> (36.3626, 29.3979)
  curve K34 (33.8046, 27.9941) -> (34.3714, 28.522)
  curve K35 (33.3789, 27.6155) -> (33.8046, 27.9941)
  curve K36 (33.2234, 27.417) -> (33.3789, 27.6155)
  curve K37 (32.1327, 28.7369) -> (31.5065, 29.0091)
  curve K38 (31.4881, 30.0752) -> (30.7329, 29.7314)
  curve K39 (38.8816, 27.3228) -> (39.5631, 27.0118)
  curve K40 (38.5849, 28.5425) -> (38.8816, 27.3228)
  curve K41 (40.2875, 29.6967) -> (39.9867, 29.977)
  curve K42 (40.4737, 29.2505) -> (40.2875, 29.6967)
  curve K43 (40.5413, 28.5425) -> (40.4737, 29.2505)
  curve K44 (40.4328, 27.6892) -> (40.5413, 28.5425)
  curve K45 (40.1074, 27.1878) -> (40.4328, 27.6892)
  curve K46 (39.5631, 27.0118) -> (40.1074, 27.1878)
  line L39 (34.6947, 27.417) -> (33.2234, 27.417)
  line L40 (34.6947, 27.063) -> (34.6947, 27.417)
  line L41 (32.7118, 27.063) -> (34.6947, 27.063)
  curve K47 (34.3121, 29.2505) -> (34.1402, 28.8065)
  curve K48 (34.1545, 29.6189) -> (34.3121, 29.2505)
  curve K49 (33.7473, 29.7703) -> (34.1545, 29.6189)
  curve K50 (33.3216, 29.6107) -> (33.7473, 29.7703)
  curve K51 (33.16, 29.1687) -> (33.3216, 29.6107)
  line L42 (32.7814, 29.2076) -> (33.16, 29.1687)
  curve K52 (33.074, 29.8522) -> (32.7814, 29.2076)
  curve K53 (33.7555, 30.0752) -> (33.074, 29.8522)
  curve K54 (34.4389, 29.8358) -> (33.7555, 30.0752)
  curve K55 (34.6907, 29.2424) -> (34.4389, 29.8358)
  curve K56 (34.617, 28.8883) -> (34.6907, 29.2424)
  curve K57 (34.3714, 28.522) -> (34.617, 28.8883)
  curve K58 (36.5508, 27.3228) -> (37.2323, 27.0118)
  curve K59 (36.2541, 28.5425) -> (36.5508, 27.3228)
  curve K60 (37.9567, 29.6967) -> (37.6559, 29.977)
  curve K61 (38.1429, 29.2505) -> (37.9567, 29.6967)
  curve K62 (38.2104, 28.5425) -> (38.1429, 29.2505)
  curve K63 (38.102, 27.6892) -> (38.2104, 28.5425)
  curve K64 (37.7766, 27.1878) -> (38.102, 27.6892)
  curve K65 (37.2323, 27.0118) -> (37.7766, 27.1878)
  line L43 (35.7159, 27.063) -> (35.7159, 27.4825)
  line L44 (35.2964, 27.063) -> (35.7159, 27.063)
  line L45 (35.2964, 27.4825) -> (35.2964, 27.063)
  line L46 (35.7159, 27.4825) -> (35.2964, 27.4825)
  curve K66 (32.3926, 28.037) -> (32.1327, 28.7369)
  curve K67 (32.2698, 27.5111) -> (32.3926, 28.037)
  curve K68 (31.9362, 27.1407) -> (32.2698, 27.5111)
  curve K69 (31.4533, 27.0118) -> (31.9362, 27.1407)
  curve K70 (30.7023, 27.3495) -> (31.4533, 27.0118)
  curve K71 (30.4117, 28.4668) -> (30.7023, 27.3495)
  dimension "d239" Text1-Height = 3
sketch "Sketch4" plane through (40, 0, 0) normal (1, 0, 0) x axis (0, 1, 0)
  line L1 (44.7318, 53.9359) -> (48.9918, 53.9359)
  line L2 (44.7318, 45.6759) -> (44.7318, 53.9359)
  line L3 (48.9918, 45.6759) -> (44.7318, 45.6759)
  line L4 (48.9918, 47.1259) -> (48.9918, 45.6759)
  line L5 (55.6118, 47.1259) -> (48.9918, 47.1259)
  line L6 (55.6118, 52.4859) -> (55.6118, 47.1259)
  line L7 (48.9918, 52.4859) -> (55.6118, 52.4859)
  line L8 (48.9918, 53.9359) -> (48.9918, 52.4859)
  circle C1 centre (44.7318, 49.8059) radius 0.85
  point P10 (44.7318, 49.8059)
  midpoint L2 P10
  dimension "d241" diameter C1 = 1.7 (= "filament_hole_width")
extrude "Extrude4" cut sketch "Sketch4" profile of L2 C1 no distance stored
sketch "Sketch15" plane through (-11, 0, 0) normal (-1, 0, 0) x axis (0, -1, 0)
  line L1 (-19.6118, 60) -> (-19.6118, 23.2332)
  line L2 (-39.6118, 60) -> (-19.6118, 60)
  line L3 (-39.6118, 52.6059) -> (-39.6118, 60)
  line L4 (-33.1118, 52.6059) -> (-39.6118, 52.6059)
  line L5 (-33.1118, 54.0559) -> (-33.1118, 52.6059)
  line L6 (-28.6118, 54.0559) -> (-33.1118, 54.0559)
  line L7 (-28.6118, 45.5559) -> (-28.6118, 54.0559)
  line L8 (-33.1118, 45.5559) -> (-28.6118, 45.5559)
  line L9 (-33.1118, 47.0059) -> (-33.1118, 45.5559)
  line L10 (-39.6118, 47.0059) -> (-33.1118, 47.0059)
  line L11 (-39.6118, 39.6118) -> (-39.6118, 47.0059)
  line L12 (-22.1725, 22.1725) -> (-39.6118, 39.6118)
  arc A1 centre (-21.1118, 23.2332) radius 1.5 clockwise from (-19.6118, 23.2332) to (-22.1725, 22.1725)
  circle C1 centre (-28.6118, 49.8059) radius 0.85
  point P16 (-28.6118, 49.8059)
  midpoint L7 P16
  dimension "d244" diameter C1 = 1.7 (= "filament_hole_width")
sketch "Sketch9" plane through (62, 0, 0) normal (1, 0, 0) x axis (0, 1, 0)
  line L1 (49.1118, 47.0059) -> (55.6118, 47.0059)
  line L2 (49.1118, 45.5559) -> (49.1118, 47.0059)
  line L3 (44.6118, 45.5559) -> (49.1118, 45.5559)
  line L4 (44.6118, 54.0559) -> (44.6118, 45.5559)
  line L5 (49.1118, 54.0559) -> (44.6118, 54.0559)
  line L6 (49.1118, 52.6059) -> (49.1118, 54.0559)
  line L7 (55.6118, 52.6059) -> (49.1118, 52.6059)
  line L8 (55.6118, 60) -> (55.6118, 52.6059)
  line L9 (39.6118, 60) -> (55.6118, 60)
  line L10 (39.6118, 52.4859) -> (39.6118, 60)
  line L11 (32.9918, 52.4859) -> (39.6118, 52.4859)
  line L12 (32.9918, 53.9359) -> (32.9918, 52.4859)
  line L13 (28.7318, 53.9359) -> (32.9918, 53.9359)
  line L14 (28.7318, 45.6759) -> (28.7318, 53.9359)
  line L15 (32.9918, 45.6759) -> (28.7318, 45.6759)
  line L16 (32.9918, 47.1259) -> (32.9918, 45.6759)
  line L17 (39.6118, 47.1259) -> (32.9918, 47.1259)
  line L18 (39.6118, 10) -> (39.6118, 47.1259)
  line L19 (55.6118, 10) -> (39.6118, 10)
  line L20 (55.6118, 47.0059) -> (55.6118, 10)
  circle C1 centre (28.7318, 49.8059) radius 0.85
  circle C2 centre (44.6118, 49.8059) radius 0.85
  point P22 (28.7318, 49.8059)
  point P23 (44.6118, 49.8059)
  midpoint L14 P22
  midpoint L4 P23
  dimension "d247" diameter C1 = 1.7 (= "filament_hole_width")
  dimension "d250" diameter C2 = 1.7 (= "filament_hole_width")
extrude "Extrude12" cut sketch "Sketch9" profile of L4 L14 C1 C2 no distance stored
sketch "Sketch16" plane through (0, 19.6118, 0) normal (0, -1, 0) x axis (1, 0, 0)
  dimension "d253" = 3
extrude "Extrude22" cut sketch "Sketch16" against normal blind 2
extrude "Extrude23" cut sketch "Sketch15" profile of L7 C1 against normal blind 2000
sketch "Sketch17" plane through (0, 19.6118, 0) normal (0, -1, 0) x axis (1, 0, 0)
  line L1 (0, 60) -> (40, 60)
  line L2 (40, 23.2332) -> (0, 23.2332)
  curve K1
  curve K2
  curve K3
  curve K4
  line L3 (40, 60) -> (40, 23.2332)
  line L4 (0, 23.2332) -> (0, 60)
  line L5 (11.6431, 40.0635) -> (12.45, 42.2427)
  line L6 (11.2993, 40.061) -> (11.6431, 40.0635)
  line L7 (10.4569, 42.2283) -> (11.2993, 40.061)
  line L8 (10.8457, 42.2311) -> (10.4569, 42.2283)
  line L9 (11.3216, 40.933) -> (10.8457, 42.2311)
  curve K5 (11.4639, 40.4961) -> (11.3216, 40.933)
  curve K6 (11.5981, 40.9104) -> (11.4639, 40.4961)
  line L10 (12.0714, 42.2399) -> (11.5981, 40.9104)
  line L11 (12.45, 42.2427) -> (12.0714, 42.2399)
  line L12 (16.1037, 40.9962) -> (16.101, 41.3666)
  line L13 (14.9721, 40.988) -> (16.1037, 40.9962)
  line L14 (14.9694, 41.3584) -> (14.9721, 40.988)
  line L15 (16.101, 41.3666) -> (14.9694, 41.3584)
  curve K7 (27.6899, 42.5144) -> (27.5876, 41.6582)
  curve K8 (28.0116, 43.0181) -> (27.6899, 42.5144)
  curve K9 (28.5547, 43.198) -> (28.0116, 43.0181)
  curve K10 (28.979, 43.1028) -> (28.5547, 43.198)
  curve K11 (21.7665, 40.3924) -> (21.7253, 40.1363)
  curve K12 (22.005, 40.7932) -> (21.7665, 40.3924)
  curve K13 (22.4847, 41.251) -> (22.005, 40.7932)
  curve K14 (23.1411, 41.8901) -> (22.4847, 41.251)
  curve K15 (25.3591, 42.4976) -> (25.2568, 41.6414)
  curve K16 (25.6809, 43.0013) -> (25.3591, 42.4976)
  curve K17 (26.2239, 43.1812) -> (25.6809, 43.0013)
  curve K18 (26.6482, 43.086) -> (26.2239, 43.1812)
  line L16 (20.9705, 42.3676) -> (21.3365, 42.3989)
  curve K19 (20.829, 42.6818) -> (20.9705, 42.3676)
  curve K20 (20.4595, 42.8367) -> (20.829, 42.6818)
  curve K21 (20.1513, 42.7362) -> (20.4595, 42.8367)
  curve K22 (19.8797, 42.3639) -> (20.1513, 42.7362)
  curve K23 (19.7804, 41.6694) -> (19.8797, 42.3639)
  curve K24 (20.1036, 41.9726) -> (19.7804, 41.6694)
  curve K25 (20.506, 42.0737) -> (20.1036, 41.9726)
  curve K26 (19.7273, 42.7905) -> (19.4151, 41.5235)
  curve K27 (21.0604, 42.9454) -> (20.4799, 43.1397)
  curve K28 (21.3365, 42.3989) -> (21.0604, 42.9454)
  line L17 (17.3032, 40.1044) -> (17.7311, 41.7794)
  line L18 (16.9185, 40.1016) -> (17.3032, 40.1044)
  line L19 (16.2377, 42.27) -> (16.9185, 40.1016)
  line L20 (16.6184, 42.2728) -> (16.2377, 42.27)
  line L21 (16.9733, 41.0209) -> (16.6184, 42.2728)
  line L22 (17.1055, 40.5552) -> (16.9733, 41.0209)
  curve K29 (17.2149, 41.0042) -> (17.1055, 40.5552)
  line L23 (17.5515, 42.2795) -> (17.2149, 41.0042)
  line L24 (17.9301, 42.2822) -> (17.5515, 42.2795)
  line L25 (18.2645, 41.024) -> (17.9301, 42.2822)
  line L26 (18.376, 40.6094) -> (18.2645, 41.024)
  line L27 (18.4978, 41.0298) -> (18.376, 40.6094)
  line L28 (18.8611, 42.289) -> (18.4978, 41.0298)
  line L29 (19.2192, 42.2915) -> (18.8611, 42.289)
  line L30 (18.5556, 40.1134) -> (19.2192, 42.2915)
  line L31 (18.1729, 40.1107) -> (18.5556, 40.1134)
  line L32 (17.8177, 41.4096) -> (18.1729, 40.1107)
  line L33 (17.7311, 41.7794) -> (17.8177, 41.4096)
  line L34 (14.0544, 43.0933) -> (13.817, 43.0916)
  line L35 (14.0761, 40.0811) -> (14.0544, 43.0933)
  line L36 (13.7078, 40.0784) -> (14.0761, 40.0811)
  line L37 (13.6909, 42.4256) -> (13.7078, 40.0784)
  curve K30 (13.3428, 42.1693) -> (13.6909, 42.4256)
  curve K31 (12.9574, 41.9762) -> (13.3428, 42.1693)
  line L38 (12.9548, 42.3323) -> (12.9574, 41.9762)
  curve K32 (13.4925, 42.6881) -> (12.9548, 42.3323)
  curve K33 (13.817, 43.0916) -> (13.4925, 42.6881)
  curve K34 (22.8113, 41.0753) -> (23.3744, 41.6073)
  curve K35 (22.3884, 40.6937) -> (22.8113, 41.0753)
  curve K36 (22.2344, 40.494) -> (22.3884, 40.6937)
  curve K37 (21.1341, 41.806) -> (20.506, 42.0737)
  curve K38 (20.4799, 43.1397) -> (19.7273, 42.7905)
  curve K39 (27.8931, 40.4408) -> (28.5768, 40.1346)
  curve K40 (27.5876, 41.6582) -> (27.8931, 40.4408)
  curve K41 (29.2818, 42.8247) -> (28.979, 43.1028)
  curve K42 (29.4713, 42.3799) -> (29.2818, 42.8247)
  curve K43 (29.5439, 41.6724) -> (29.4713, 42.3799)
  curve K44 (29.4416, 40.8183) -> (29.5439, 41.6724)
  curve K45 (29.1199, 40.3146) -> (29.4416, 40.8183)
  curve K46 (28.5768, 40.1346) -> (29.1199, 40.3146)
  line L39 (23.7057, 40.5047) -> (22.2344, 40.494)
  line L40 (23.7082, 40.1506) -> (23.7057, 40.5047)
  line L41 (21.7253, 40.1363) -> (23.7082, 40.1506)
  curve K47 (23.3098, 42.3354) -> (23.1411, 41.8901)
  curve K48 (23.1495, 42.7026) -> (23.3098, 42.3354)
  curve K49 (22.7412, 42.8511) -> (23.1495, 42.7026)
  curve K50 (22.3167, 42.6884) -> (22.7412, 42.8511)
  curve K51 (22.1583, 42.2452) -> (22.3167, 42.6884)
  line L42 (21.7794, 42.2814) -> (22.1583, 42.2452)
  curve K52 (22.0674, 42.9281) -> (21.7794, 42.2814)
  curve K53 (22.7472, 43.1561) -> (22.0674, 42.9281)
  curve K54 (23.4324, 42.9216) -> (22.7472, 43.1561)
  curve K55 (23.6884, 42.33) -> (23.4324, 42.9216)
  curve K56 (23.6173, 41.9754) -> (23.6884, 42.33)
  curve K57 (23.3744, 41.6073) -> (23.6173, 41.9754)
  curve K58 (25.5624, 40.4239) -> (26.246, 40.1178)
  curve K59 (25.2568, 41.6414) -> (25.5624, 40.4239)
  curve K60 (26.9511, 42.8078) -> (26.6482, 43.086)
  curve K61 (27.1405, 42.3631) -> (26.9511, 42.8078)
  curve K62 (27.2131, 41.6555) -> (27.1405, 42.3631)
  curve K63 (27.1108, 40.8014) -> (27.2131, 41.6555)
  curve K64 (26.7891, 40.2977) -> (27.1108, 40.8014)
  curve K65 (26.246, 40.1178) -> (26.7891, 40.2977)
  line L43 (24.7293, 40.158) -> (24.7263, 40.5775)
  line L44 (24.3098, 40.155) -> (24.7293, 40.158)
  line L45 (24.3068, 40.5745) -> (24.3098, 40.155)
  line L46 (24.7263, 40.5775) -> (24.3068, 40.5745)
  curve K66 (21.3991, 41.1081) -> (21.1341, 41.806)
  curve K67 (21.2801, 40.5813) -> (21.3991, 41.1081)
  curve K68 (20.9492, 40.2085) -> (21.2801, 40.5813)
  curve K69 (20.4672, 40.0761) -> (20.9492, 40.2085)
  curve K70 (19.7138, 40.4083) -> (20.4672, 40.0761)
  curve K71 (19.4151, 41.5235) -> (19.7138, 40.4083)
  circle C1 centre (20, 49.8059) radius 1.06
  point P2 (40, 23.2332)
  point P4 (0, 60)
  coincident P2
  coincident P4
  dimension "d258" Text1-Height = 3
extrude "Extrude24" cut sketch "Sketch17" against normal blind 2
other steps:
create_component "CreateComponent1"
create_component "CreateComponent2"
create_component "CreateComponent3"
create_component "CreateComponent4"
named bodies: "Wall anchor part", "Base plate with slot"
